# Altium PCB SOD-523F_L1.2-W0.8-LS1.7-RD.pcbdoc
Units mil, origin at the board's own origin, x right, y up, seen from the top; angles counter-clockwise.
Board outline 580 x 538 mil, 2 copper layers (Top Layer, Bottom Layer), stack 0 mil thick; 1 components, 0 nets, 2 pads, 0 vias.
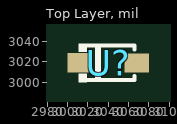
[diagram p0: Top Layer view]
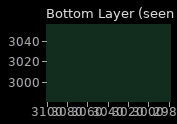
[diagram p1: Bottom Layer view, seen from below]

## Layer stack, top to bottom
Top Layer: signal copper (thickness not stored)
Bottom Layer: signal copper (thickness not stored)

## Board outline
3330,2750 2750,2750 2750,3288 3330,3288

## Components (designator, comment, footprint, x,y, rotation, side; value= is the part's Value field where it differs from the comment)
U? "" SOD-523F_L1.2-W0.8-LS1.7-RD 3040.01,3019 r0 top

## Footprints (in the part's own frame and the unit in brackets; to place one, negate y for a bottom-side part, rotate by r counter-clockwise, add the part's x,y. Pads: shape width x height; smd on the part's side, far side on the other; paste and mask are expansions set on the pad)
SOD-523F_L1.2-W0.8-LS1.7-RD [mil]
  rect 24x19 smd: 1(-28,0.2) 2(28,-0.2)
  silkscreen extent -29,-19 26,19

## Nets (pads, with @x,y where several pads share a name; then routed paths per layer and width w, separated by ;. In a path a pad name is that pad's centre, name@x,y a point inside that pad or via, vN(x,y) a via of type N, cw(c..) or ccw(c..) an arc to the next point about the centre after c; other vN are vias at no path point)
pads on no net: U?.1 U?.2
